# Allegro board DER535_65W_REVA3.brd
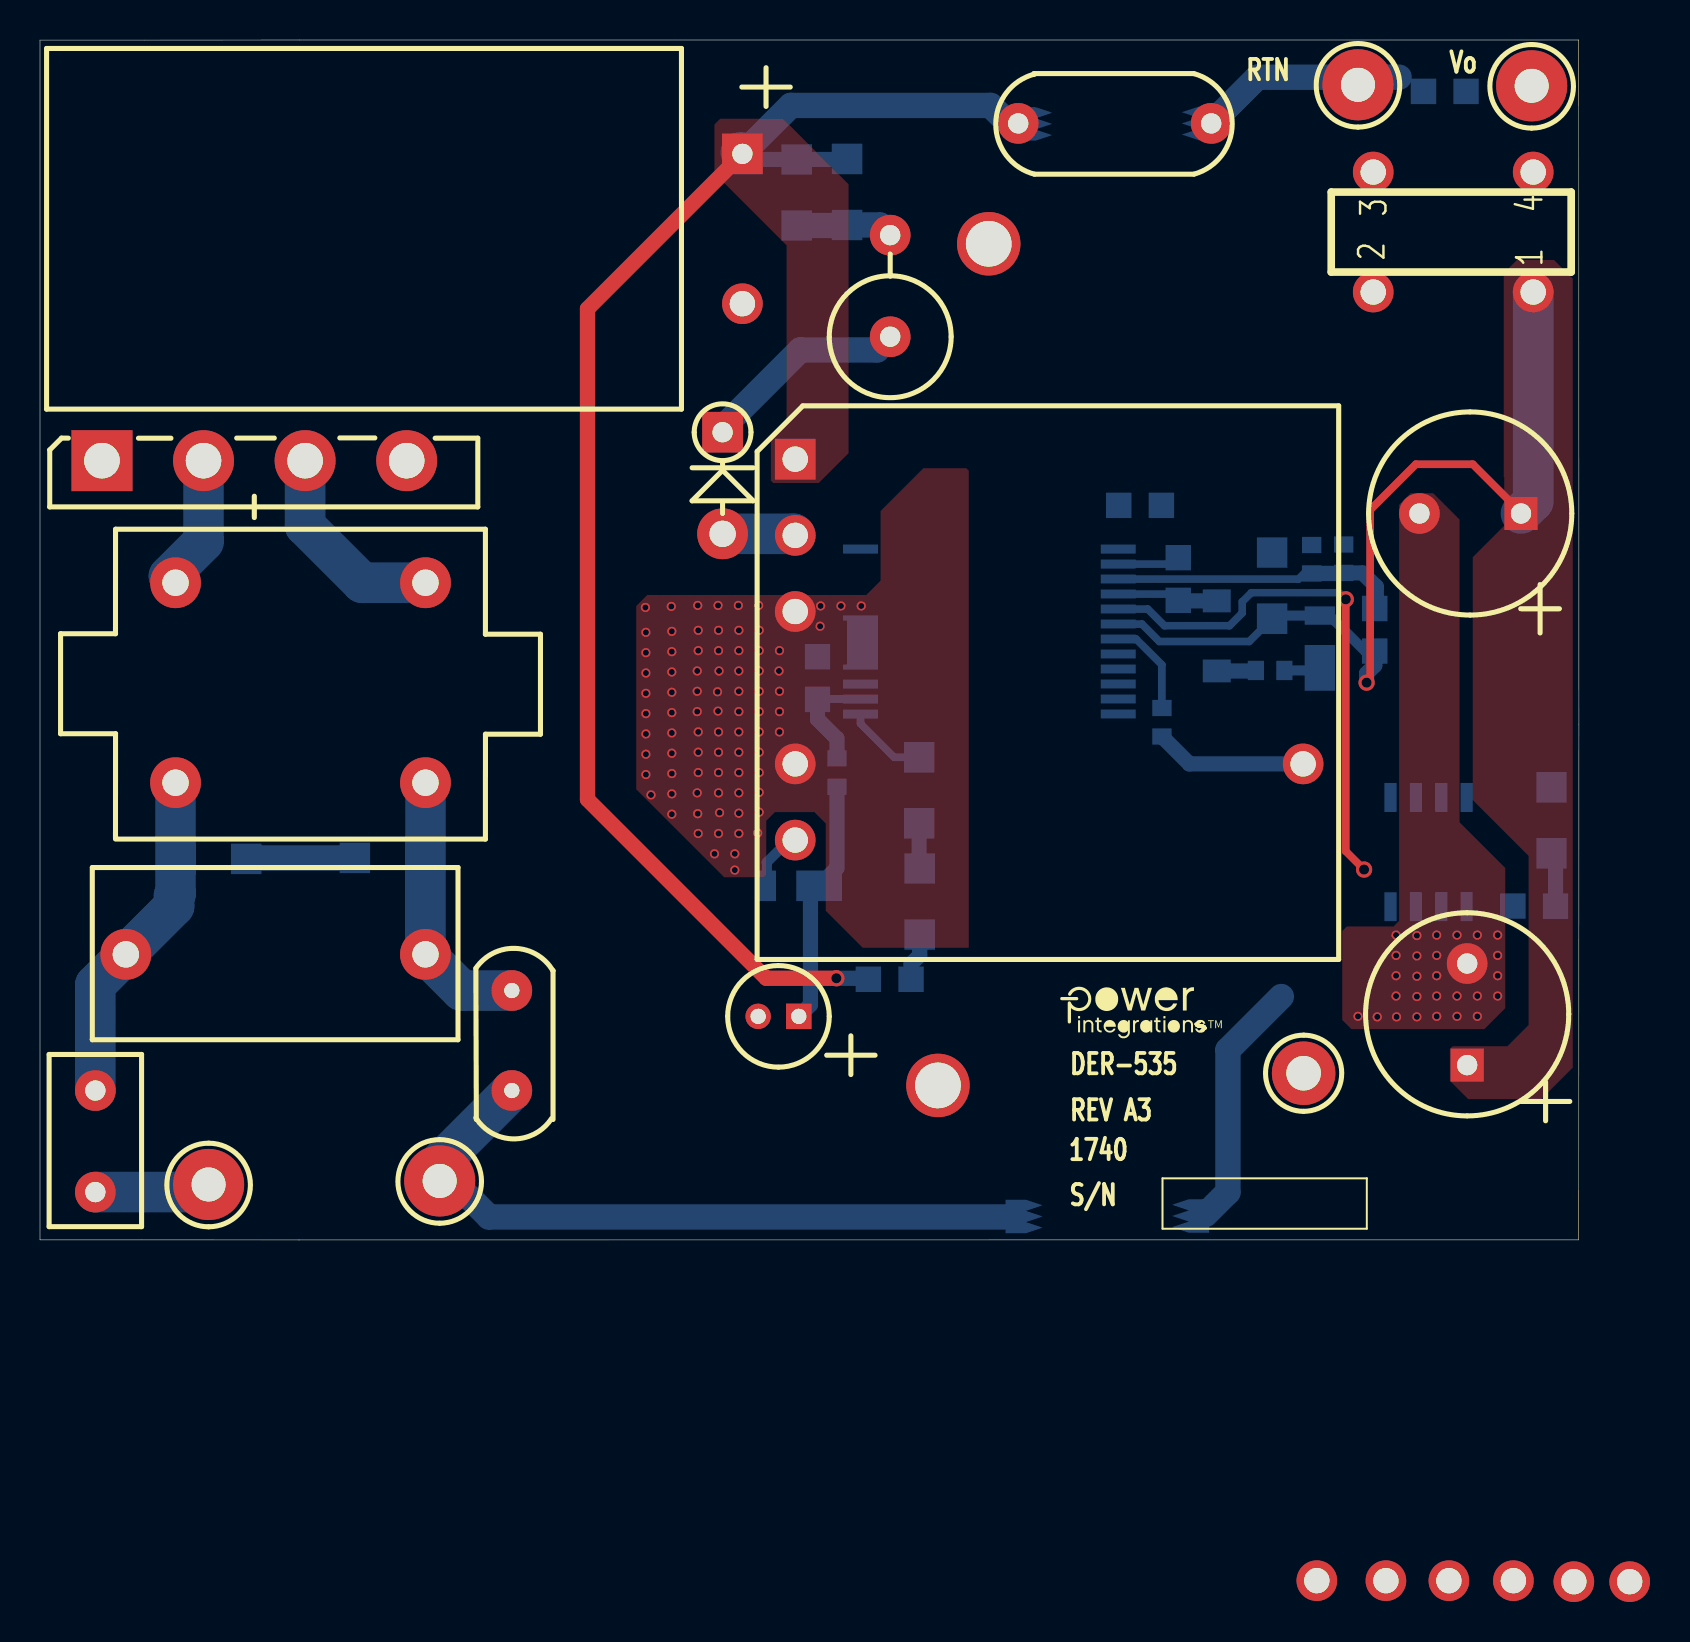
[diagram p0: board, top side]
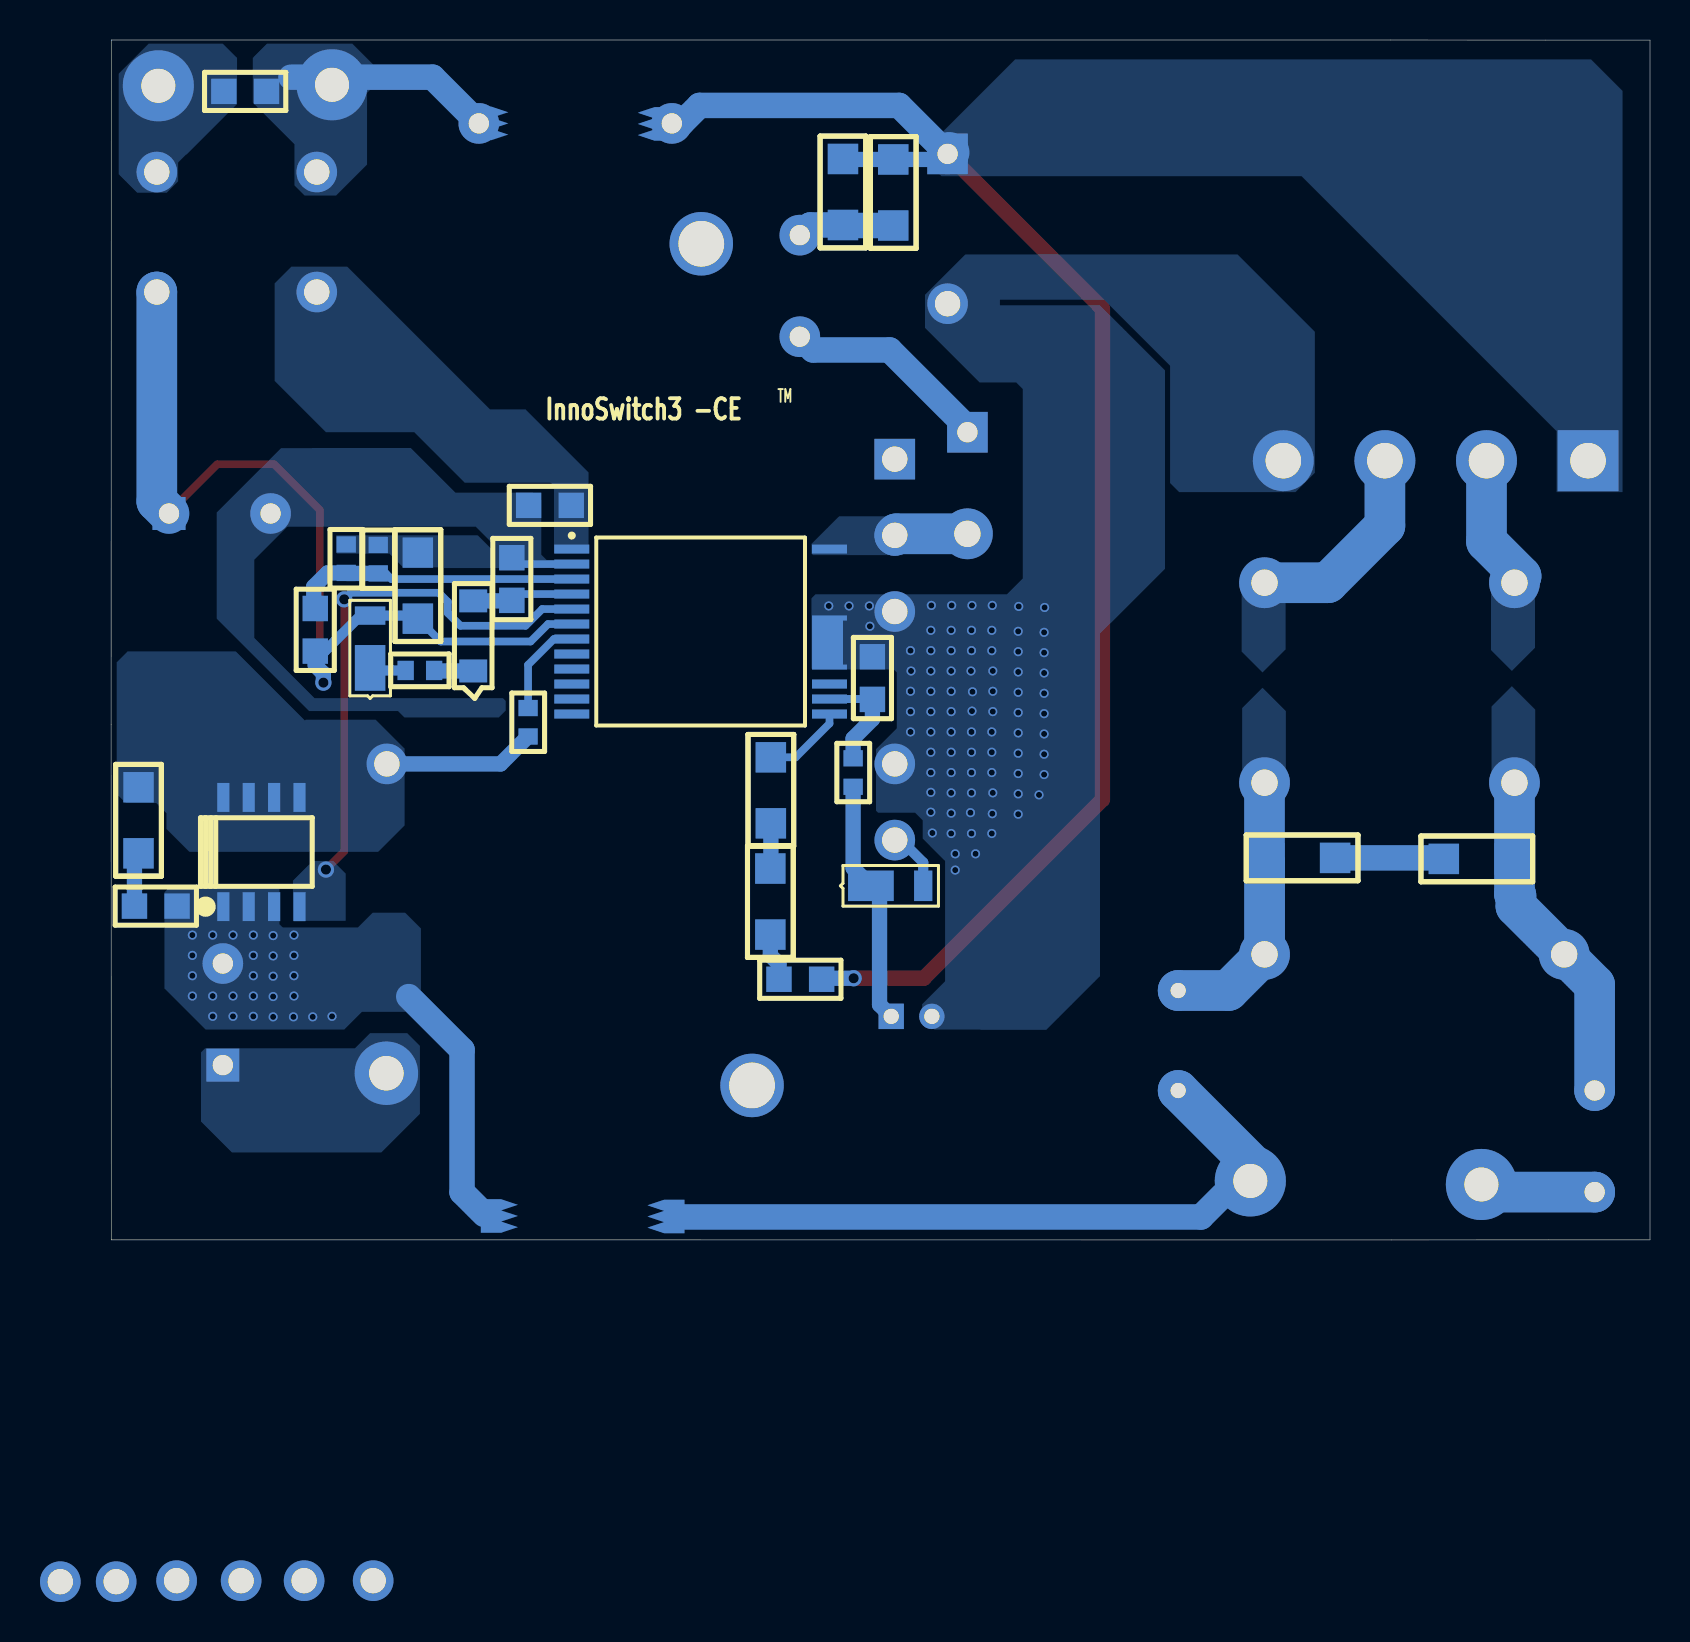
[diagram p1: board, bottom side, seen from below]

Outline 76.96 x 60 mm; copper layers: TOP, BOTTOM. Coordinates in mm from the lower left corner of the outline.
Outline path: 0,60 5.23,60 12.95,60 76.95,60 76.96,25.79 76.95,0 12.95,0 5.08,0 0,0 0,60

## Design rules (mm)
constraint set DEFAULT: min track width 0.508

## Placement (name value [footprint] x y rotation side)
BR1  GBU4J-BP  [PIDAXBRIDGEGBU8]  3.1 38.97 0 top
C1  220 nF  [PINPXCAPRAD720X340590040]  4.29 14.28 0 top
C2  120 uF  [PIPOLCAPD710LS3000401400LHORIZ]  35.13 54.31 270 top
C3  2.2 nF  [PISMC1206]  37.85 50.73 90 bottom
C4  22 uF  [PIPOLCAPCLYD200LS80030]  37.95 11.18 180 top
C5  4.7 uF  [PISMC0805]  38.89 27.03 90 bottom
C6  680 pF  [PINPYCAPRAD470X210LS380040]  48.92 55.83 0 top
C7  2.2 uF  [PISMC0805]  56.92 34.12 270 bottom
C8  10 nF  [PISMC1206]  61.62 34.37 270 bottom
C9  330 pF  [PISMC0603]  63.6 34.75 270 bottom
C10  2.2 nF  [PISMC0805]  75.79 16.69 180 bottom
C11  560 uF  [PIPOLCAPCYLD400LS200040]  71.37 8.74 90 top
C12  560 uF  [PIPOLCAPCYLD400LS200040]  74.07 36.33 180 top
C14  1 uF  [PISMC0805]  71.32 57.43 180 bottom
D1  FR107G  [PIDV200X110X040DO41]  34.14 40.39 270 top
D2  DFLR1200-7  [PISMDDFLR120012]  38.99 17.71 0 bottom
D3  DFLR1200-7  [PISMDDFLR120012]  64.01 28.58 270 bottom
F1  3.15 A  [PI_RST_MICROFUSE]  2.77 7.47 270 top
FL1  Hole_70mils  [PI_HOLE_70MIL]  63.2 8.31 0 top
L  BLK  [PITPKEYSTONE125X125]  8.43 2.77 0 top
L1  15 mH  [PIIND4P944X650LS492X394031]  19.28 22.86 180 top
L2  155 uH  [PI_TOROID_CMC_DER535]  74.68 47.4 90 top
MTG_HOLE1  No 2  [PIMTGHOLE2]  47.45 49.81 0 top
MTG_HOLE2  No 2  [PIMTGHOLE2]  44.91 7.73 0 top
N  WHT  [PITPKEYSTONE125X125]  19.99 2.95 0 top
NOREF  -  []  -137.83 54.24 0 top
NOREF#2  -  []  50.47 12.55 0 top
NOREF#3  -  []  0 60 0 top
NOREF#4  -  []  0 0 90 top
NOREF#5  -  []  -215.65 -144.78 0 top
Q1  AO4294  [PISMSO8]  71.35 16.67 180 bottom
R1  1.5 M  [PISMR1206]  7.01 19.05 0 bottom
R2  2 M  [PISMR1206]  15.75 19.11 0 bottom
R3  100 k  [PISMR1206]  40.36 54.06 270 bottom
R4  47  [PI_2W_VRES240LS200D040]  42.52 45.17 90 top
R5  5.1 k  [PISMR0603]  39.85 22.66 90 bottom
R6  49.9 k  [PISMR0805]  41.43 13.03 0 bottom
R7  1.80 M  [PISMR1206]  43.99 15.27 90 bottom
R8  1.80 M  [PISMR1206]  43.97 20.83 90 bottom
R9  47  [PISMR0603]  56.11 25.18 90 bottom
R10  0.007  [PISMR0805]  56.08 36.73 180 bottom
R11  12  [PISMR1206]  75.59 19.33 90 bottom
R12  100  [PISMR0603]  60.81 28.48 0 bottom
R13  143 k  [PISMR0805]  66.75 29.44 90 bottom
R14  10 k  [PISMR0603]  65.2 33.35 90 bottom
RT1  2.5  [PI_RAD150X300LS200D030]  23.6 7.47 90 top
T1  PQ26/20  [PI_BOBBIN_BPQ26_20_12P]  37.77 39.04 0 top
TP3  RED  [PITPKEYSTONE125X125]  74.6 57.71 0 top
TP4  BLK  [PITPKEYSTONE125X125]  65.91 57.76 0 top
U1  INN3168C  [PI_IC_INSOP_24B]  53.92 34.55 180 bottom
VR1  MMSZ5248B-7-F  [PI_SM_SOD-123_12]  58.85 28.45 90 bottom

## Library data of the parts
BR1 = DISCRETE BRIDGE_+~~-
C1 C3 C5-C10 C14 = CAP NP
C2 = CAP POL: alternate symbols: (pipolcapd710ls3000401400lhoriz)
C4 = CAP POL: alternate symbols: (pipolcapclyd200ls80030h)
C11 C12 = CAP POL: alternate symbols: (pipolcapcyld400ls2000401000h)
D1 = DIODE: alternate symbols: (pidax475x125040do41,pidv200x110x040do41wbead,pidax390x125040do41)
D2 D3 = DIODE
F1 = FUSE: alternate symbols: (pirstmicrofusehoz)
FL1 = FlyingLead
L N TP3 TP4 = TESTPOINT
L1 = INDUCTOR_4P_revD
L2 = TORRID 4P_14_23
MTG_HOLE1 MTG_HOLE2 = MTG_HOLE_2-56
Q1 = FET_N_SGD_123_4_5678
R1-R3 R5-R14 = R
R4 = R: alternate symbols: (PI_2W_RES240LS500D040,pi_2w_resd145ls455d040)
RT1 = THERMISTOR: alternate symbols: (pirad400x300ls200040_h)
T1 = BPQ26/20_12P/GENERIC
U1 = DEV_InSOP_0
VR1 = DIODE_ZENER

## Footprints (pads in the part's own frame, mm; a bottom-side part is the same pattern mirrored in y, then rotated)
PI_2W_VRES240LS200D040
  round 2.032 hole 1.016: 1(0,0) 2(5.08,0)
PI_BOBBIN_BPQ26_20_12P
  rect 2.032x2.032 hole 1.27: 1(0,0)
  round 2.032 hole 1.27: 2(0,-3.81) 3(0,-7.62) 4(0,-15.24) 5(0,-19.05) 6(26.086,-56.083) 7(32.69,-56.083) 8(29.54,-56.083) 9(25.4,-15.24) 10(41.732,-56.134) 11(38.938,-56.134) 12(35.916,-56.083)
PI_HOLE_70MIL
  round 3.175 hole 1.727: 1(0,0.025)
PI_IC_INSOP_24B
  rect 1.75x0.45 smd: 1(0,0) 2(0,-0.75) 3(0,-1.5) 4(0,-2.25) 5(0,-3) 6(0,-3.75) 7(0,-4.5) 8(0,-5.25) 9(0,-6) 10(0,-6.75) 11(0,-7.5) 12(0,-8.25) 13(12.89,-8.25) 14(12.89,-7.5) 15(12.89,-6.75) 24(12.89,0)
  custom 0.437x0.437 smd: 16(12.89,-4.67)
PI_RAD150X300LS200D030
  round 2.032 hole 0.762: 1(0,0) 2(5,0)
PI_RST_MICROFUSE
  round 2.032 hole 1.016: 1(0,0) 2(5.08,0)
PI_SM_SOD-123_12
  rect 1.143x1.397 smd: 1(0,0) 2(3.505,0)
PI_TOROID_CMC_DER535
  round 2.032 hole 1.27: 1(0,0) 2(0,8) 3(6,8) 4(6,0)
PIDAXBRIDGEGBU8
  rect 3.048x3.048 hole 1.778: 1(0,0)
  round 3.048 hole 1.778: 2(5.08,0) 3(10.16,0) 4(15.24,0)
PIDV200X110X040DO41
  rect 2.032x2.032 hole 1.016: 1(0,0)
  round 2.54 hole 1.321: 2(5.08,0)
PIIND4P944X650LS492X394031
  round 2.54 hole 1.321: 1(12.5,-10) 2(12.5,0) 3(0,0) 4(0,-10)
PIMTGHOLE2
  round 3.175 hole 2.286: 1(0,0)
PINPXCAPRAD720X340590040
  round 2.54 hole 1.321: 1(0,0) 2(14.986,0)
PINPYCAPRAD470X210LS380040
  round 2.032 hole 1.016: 1(0,0) 2(9.652,0)
PIPOLCAPCLYD200LS80030
  rect 1.27x1.27 hole 0.762: 1(0,0)
  round 1.27 hole 0.762: 2(2.032,0)
PIPOLCAPCYLD400LS200040
  rect 1.651x1.651 hole 1.016: 1(0,0)
  round 2.032 hole 1.016: 2(5.08,0)
PIPOLCAPD710LS3000401400LHORIZ
  rect 2.032x2.032 hole 1.016: 1(0,0)
  round 2.032 hole 1.27: 2(7.493,0)
PISMC0603
  rect 0.813x0.965 smd: 1(0,0) 2(1.422,0)
PISMC0805
  rect 1.27x1.27 smd: 1(0,0) 2(2.134,0)
PISMC1206
  rect 1.524x1.524 smd: 1(0,0) 2(3.302,0)
PISMDDFLR120012
  rect 2.286x1.524 smd: 1(-0.025,0)
  rect 0.914x1.524 smd: 2(-2.642,0)
PISMR0603
  rect 0.813x0.965 smd: 1(0,0) 2(1.422,0)
PISMR0805
  rect 1.27x1.27 smd: 1(0,0) 2(2.134,0)
PISMR1206
  rect 1.524x1.524 smd: 1(0,0) 2(3.302,0)
PISMSO8
  rect 0.61x1.448 smd: 1(0,0) 2(1.27,0) 3(2.54,0) 4(3.81,0) 5(3.81,5.461) 6(2.54,5.461) 7(1.27,5.461) 8(0,5.461)
PITPKEYSTONE125X125
  round 3.556 hole 1.702: 1(0,0)

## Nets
NC8: U1.8
NC9: U1.9
NC10: U1.10
NC11: U1.11
NC12: U1.12
NC15: U1.15
N2987702: BR1.1 C2.1 C3.2 C6.1 R3.1 R6.1 T1.1
N2987790: BR1.2 L1.1
N2987798: N.1 RT1.1
N2987826: F1.2 L.1
N10910152: R9.2 U1.7
N10910164: C3.1 R3.2 R4.2
N10910168: L2.2 R10.2 U1.1
N10910222: C7.1 C8.1 C9.1 C10.2 C11.2 C12.2 Q1.1 Q1.2 Q1.3(S3) R10.1 R14.2 U1.2
N10910248: Q1.4 U1.5
N10910298: C5.1 R5.2 U1.14
N10910306: C8.2 C11.1 C12.1 D3.2 FL1.1 L2.1 R13.1 U1.6
N10910326: BR1.4 C2.2 C4.2 C5.2 T1.3 T1.4 U1.16
N10910384: C9.2 R13.2 R14.1 U1.3
N10910392: R8.2 U1.13(VPIN)
N10910464: D2.2 T1.5
N10910558: C10.1 R11.1
N10910618: R7.2 R8.1
N10910664: C6.2 C14.2 L2.3 TP4.1
N10911024: C7.2 U1.4 VR1.2
N10911106: C4.1 D2.1 R5.1
N10913618: D1.1 R4.1
N10913908: D1.2 T1.2 U1.24
N10921396: C1.2 L1.3 R2.2 RT1.2
N10932979: C14.1 L2.4 TP3.1
N10933272: Q1.5 Q1.6 Q1.7 Q1.8 R9.1 R11.2 T1.9
N10975944: C1.1 F1.1 L1.2 R1.1
N10976231: BR1.3(AC2) L1.4
N10995479: R1.2 R2.1
N11000162: R12.1 VR1.1
N11000879: R6.2 R7.1
N11102383: D3.1 R12.2

Pads without a net: MTG_HOLE1 1; MTG_HOLE2 1; T1 6 7 8 10 11 12

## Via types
v1: diameter 0.457, hole 0.305, TOP to BOTTOM, 108 vias
v2: diameter 0.813, hole 0.508, TOP to BOTTOM, 4 vias

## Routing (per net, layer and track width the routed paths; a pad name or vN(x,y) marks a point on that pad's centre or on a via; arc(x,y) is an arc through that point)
N2987702: length 73.9
  TOP w0.762: C2.1 27.38,46.56 27.38,22.03 36.32,13.09 v2(39.83,13.09)
  BOTTOM w0.762: R3.1 40.34,54.03 C3.2 35.41,54.03 C2.1 ; v2(39.83,13.09) 41.38,13.09 R6.1
  BOTTOM w1.27: C2.1 37.55,56.73 47.54,56.73 48.44,55.83 C6.1
  BOTTOM w2.032: 35.05,54.39 C2.1
N2987790: length 7
  BOTTOM w2.032: L1.1 6.45,33.19 8.18,34.92 BR1.2
N2987798: length 36.3
  BOTTOM w1.27: 19.79,3.66 19.99,3.46 N.1 ; 48.54,1.15 22.45,1.15 20.45,3.15 19.79,3.15
  BOTTOM w2.032: RT1.1 19.79,3.66 19.79,3.15
N2987826: length 6.4
  BOTTOM w1.27: 7.62,2.39 8.05,2.39 L.1
  BOTTOM w2.032: F1.2 7.62,2.39 7.9,2.67 8.13,2.67
N10910152: length 4.9
  BOTTOM w0.381: U1.7 54.82,30.05 56.11,28.76 R9.2
N10910164: length 5.1
  BOTTOM w1.27: 40.34,50.73 R3.2 42.01,50.75 R4.2 ; 40.34,50.73 40.51,50.73 ; 40.34,50.73 C3.1
N10910222: length 15.7
  BOTTOM w0.381: U1.2 56.86,33.8 56.92,33.86 C7.1
  BOTTOM w1.27: 58.29,1.27 59.41,2.39 59.41,9.5 62.08,12.17
  vias: v1(65.91,11.18) v1(66.88,11.15) v1(67.82,15.24) v1(67.82,14.23) v1(67.82,13.21) v1(67.82,12.2) v1(67.84,11.15) v1(68.86,15.22) v1(68.86,14.2) v1(68.86,13.19) v1(68.86,12.17) v1(68.86,11.15) v1(69.85,15.24) v1(69.85,14.23) v1(69.85,13.21) v1(69.85,12.2) v1(69.85,11.18) v1(70.87,15.24) v1(70.87,12.2) v1(70.87,11.18) v1(71.88,15.24) v1(71.88,12.2) v1(71.88,11.18) v1(72.9,15.24) v1(72.9,14.23) v1(72.9,13.21) v1(72.9,12.2)
N10910248: length 26.8
  TOP w0.381: v2(66.22,18.52) 65.3,19.44 v2(65.3,32.03)
  BOTTOM w0.381: v2(65.3,32.03) 64.97,32.36 60.58,32.36 60.12,31.91 60.12,31.35 59.49,30.71 56.24,30.71 55.4,31.55 U1.5
N10910298: length 7.7
  BOTTOM w0.381: 38.91,27.05 41.06,27.05 U1.14 38.91,27.05 ; 38.91,27.05 C5.1
  BOTTOM w0.762: R5.2 39.85,25.07 38.89,26.04 C5.1
N10910306: length 45.8
  TOP w0.381: v2(66.34,27.87) 66.52,28.05 66.52,36.5 68.81,38.79 71.65,38.79 74.09,36.35 C12.1
  BOTTOM w0.381: C8.2 60.48,29.93 55.98,29.93 55.11,30.8 U1.6
  BOTTOM w0.508: R13.1 66.27,29.44 64.49,31.22 D3.2 61.77,31.22 C8.2
  BOTTOM w0.762: v2(66.34,27.87) 66.34,28.33 66.75,28.73 R13.1
  BOTTOM w2.032: C12.1 74.68,36.94 L2.1
N10910326:
  vias: v1(30.28,31.63) v1(30.3,30.38) v1(30.3,29.37) v1(30.3,28.35) v1(30.3,27.33) v1(30.3,26.32) v1(30.3,25.3) v1(30.3,24.29) v1(30.3,23.27) v1(30.56,22.25) v1(31.57,31.68) v1(31.6,30.43) v1(31.6,29.42) v1(31.6,28.4) v1(31.6,27.39) v1(31.6,26.37) v1(31.6,25.35) v1(31.6,24.34) v1(31.6,23.32) v1(31.6,22.31) v1(31.6,21.29) v1(32.89,31.73) v1(32.92,30.48) v1(32.92,29.47) v1(32.87,28.45) v1(32.87,27.44) v1(32.87,26.42) v1(32.92,25.4) v1(32.92,24.39) v1(32.92,23.37) v1(32.87,22.36) v1(32.89,21.31) v1(32.92,20.32) v1(33.73,19.31) v1(33.91,31.73) v1(33.93,30.48) v1(33.93,29.47) v1(33.88,27.41) v1(33.91,26.45) v1(33.93,25.4) v1(33.93,24.39) v1(33.93,23.37) v1(33.93,22.36) v1(33.93,20.32) v1(33.96,28.45) v1(33.99,21.37) v1(34.75,19.31) v1(34.75,18.5) v1(34.92,31.73) v1(34.95,30.48) v1(34.95,29.47) v1(34.95,28.45) v1(34.95,27.44) v1(34.95,26.42) v1(34.95,25.4) v1(34.95,24.39) v1(34.95,23.37) v1(34.95,22.36) v1(34.95,21.34) v1(34.95,20.32) v1(35.94,31.73) v1(35.89,20.35) v1(35.97,30.48) v1(35.97,29.47) v1(35.97,28.45) v1(35.97,27.44) v1(35.97,26.42) v1(35.97,25.4) v1(35.97,24.39) v1(35.97,23.37) v1(35.97,22.38) v1(35.97,21.39) v1(36.98,29.47) v1(36.96,28.45) v1(36.98,27.44) v1(36.98,26.42) v1(36.98,25.4) v1(39.04,31.7) v1(39.01,30.69) v1(40.06,31.7) v1(41.07,31.7)
N10910384: length 14.4
  BOTTOM w0.381: C9.2 63.22,33.33 62.94,33.05 U1.3
  BOTTOM w0.762: R13.2 66.83,31.65 66.83,32.67 66.14,33.35 R14.1 65.18,33.33 C9.2
N10910392: length 4.1
  BOTTOM w0.381: U1.13 41.03,25.82 42.72,24.13 R8.2
N10910464: length 3.1
  BOTTOM w0.508: T1.5 37.47,19.99 36.35,18.88 D2.2
N10910558: length 2.7
  BOTTOM w0.762: C10.1 75.79,19.13 R11.1
N10910618: length 2.3
  BOTTOM w0.762: R7.2 43.97,18.6 R8.1
N10910664: length 10.9
  BOTTOM w1.27: 67.97,58.14 66.29,58.14 ; 66.29,58.14 60.88,58.14 C6.2 ; 66.29,58.14 TP4.1
N10911024: length 5.2
  BOTTOM w0.381: C7.2 56.97,32.03 56.97,32.14 56.81,32.3 U1.4
  BOTTOM w0.762: VR1.2 56.95,31.96 C7.2
N10911106: length 12.3
  BOTTOM w0.762: C4.1 38.53,11.76 38.53,17.28 D2.1 39.85,18.6 R5.1
N10913618: length 10.5
  BOTTOM w1.27: R4.1 41.86,44.51 38.02,44.51 34.14,40.62 D1.1
N10913908: length 3.7
  BOTTOM w2.032: D1.2 37.69,35.31 T1.2
N10921396: length 18.8
  BOTTOM w1.27: 19.16,14.28 18.9,14.54 18.9,18.95 R2.2
  BOTTOM w2.032: RT1.2 21.09,12.47 C1.2 19.16,14.28 19.28,14.4 L1.3
N10933272: length 7.6
  BOTTOM w0.762: T1.9 57.48,23.8 R9.1
N10975944: length 19
  BOTTOM w1.27: R1.1 6.71,18.75 6.71,17.23
  BOTTOM w2.032: L1.2 6.78,17.3 6.71,17.23 6.71,16.69 C1.1 2.77,12.76 F1.1
N10976231: length 10.5
  BOTTOM w2.032: BR1.3 13.26,35.72 16.11,32.86 L1.4
N10995479: length 5.5
  BOTTOM w1.27: R1.2 10.36,19.11 R2.1
N11000162: length 2
  BOTTOM w0.762: VR1.1 60.78,28.45 R12.1
N11000879: length 2.4
  BOTTOM w0.762: R7.1 43.99,14.23 43.56,13.8 R6.2
N11102383: length 1.8
  BOTTOM w0.508: D3.1 63.88,28.48 R12.2

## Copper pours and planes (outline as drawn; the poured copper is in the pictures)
Net_45 on BOTTOM (solid shape): 50.14,1.73 49.3,1.45 50.14,1.17 49.3,0.89 50.14,0.61 49.3,0.33 48.29,0.33 48.29,2.01 49.3,2.01
Net_45 on BOTTOM (solid shape): 50.62,56.37 49.78,56.09 50.62,55.81 49.78,55.53 50.62,55.25 49.78,54.97 48.77,54.97 48.77,56.65 49.78,56.65
Net_45 on BOTTOM (solid shape): 58.47,0.36 57.45,0.36 56.62,0.64 57.45,0.92 56.62,1.2 57.45,1.48 56.62,1.76 57.45,2.04 58.47,2.04
Net_45 on BOTTOM (solid shape): 58.95,55 57.94,55 57.1,55.27 57.94,55.55 57.1,55.83 57.94,56.11 57.1,56.39 57.94,56.67 58.95,56.67
N2987702 on TOP: 34.01,56.06 37.16,56.06 40.44,52.79 40.44,39.35 38.94,37.85 36.68,37.85 36.55,37.98 36.55,40.01 37.34,40.8 37.34,49.74 33.73,53.34 33.73,55.78
N2987702 on BOTTOM: 1.37,37.39 1.37,57.46 2.95,59.03 31.75,59.03 35.53,55.25 35.53,53.29 35.43,53.19 17.42,53.19 4.67,40.44 4.67,37.39
N2987790 on BOTTOM: 5.75,29.61 6.91,28.45 7.95,29.49 7.95,33.23 7.94,33.24 7.94,33.79 6.05,33.79 5.75,33.49
N10910168 on BOTTOM: 53.09,34.35 53.09,38.38 56.24,41.53 58.01,41.53 65.15,48.67 67.94,48.67 68.78,47.83 68.78,42.96 66.22,40.39 61.8,40.39 59.27,37.86 54.98,37.86 54.81,37.7 54.81,34.35
N10910222 on TOP: 65.35,15.68 65.13,15.45 65.13,11 65.58,10.55 72.24,10.55 73.28,11.59 73.28,18.6 70.99,20.88 70.99,36.02 69.67,37.34 68.55,37.34 67.97,36.76 67.97,15.96 67.69,15.68
N10910222 on BOTTOM: 57.78,34.24 57.94,34.24 57.94,34.55 58.62,35.23 65.71,35.23 65.71,34.37 65.66,34.32 63.04,34.32 62.36,33.63 60.6,33.63 60.58,33.61 60.58,33.6 55.26,33.6 55.12,33.74 55.12,33.94 55.45,34.27 55.45,36.99 55.83,37.37 59.74,37.37 61.98,39.6 66.9,39.6 66.92,39.59 68.47,39.59 71.68,36.38 71.68,31.07 67.06,26.45 62.61,26.45 62.29,26.13 57.57,26.13 57.23,26.47 57.23,26.95 57.37,27.09 66.79,27.09 69.8,30.1 69.8,34.01 68.15,35.67 58.72,35.67 57.78,34.73
N10910222 on BOTTOM: 72.24,10.52 65.3,10.52 64.41,11.41 62.15,11.41 61.47,12.09 61.47,15.57 62.26,16.36 63.88,16.36 64.62,15.63 68.38,15.63 68.54,15.79 68.54,17.67 68.61,17.73 73.94,17.73 74.3,17.38 74.3,12.58
N10910248 on BOTTOM: 67.84,15.96 67.87,15.98 67.87,17.96 66.88,18.95 65.86,18.95 65.23,18.32 65.23,15.98 65.25,15.96
N10910306 on TOP: 76.66,8.61 75.08,7.04 71.42,7.04 70.51,7.95 70.51,9.55 70.64,9.68 73.38,9.68 74.45,10.75 74.45,19.21 71.65,22 71.65,34.14 73.23,35.72 73.23,38.13 73.2,38.16 73.2,48.34 73.86,49 75.72,49 76.66,48.06
N10910306 on BOTTOM: 70.92,4.37 63.45,4.37 61.52,6.3 61.52,9.71 62.15,10.34 64.01,10.34 64.77,9.58 72.26,9.58 72.47,9.38 72.47,5.92
N10910326 on TOP: 36.75,21.39 38.73,21.39 39.29,20.83 39.29,16.46 41.15,14.61 46.45,14.61 46.45,38.47 46.33,38.59 44.17,38.59 42.04,36.45 42.04,32.96 41.33,32.25 30.37,32.25 29.82,31.7 29.82,22.53 34.21,18.14 36.2,18.14 36.32,18.27 36.32,20.96
N10910326 on BOTTOM: 30.19,10.51 27.51,13.19 27.51,30.31 24.26,33.56 24.26,43.49 27.51,46.74 32.51,46.74 32.51,47.02 27.3,47.02 24,43.72 24,37.85 23.55,37.39 17.73,37.39 16.76,38.36 16.76,45.42 20.62,49.28 34.24,49.28 36.26,47.26 36.26,45.61 33.53,42.88 31.7,42.88 31.37,42.55 31.37,33.07 32.16,32.29 41.73,32.29 41.94,32.08 41.94,28.58 41.88,28.53 37.82,28.53 37.67,28.38 37.67,25.58 38.71,24.54 38.71,21.47 38.61,21.37 36.75,21.37 36.37,20.98 36.37,20.07 35.26,18.95 35.26,12.93 36.4,11.79 36.4,11.13 35.79,10.52 33.5,10.52 33.49,10.51
N10910664 on BOTTOM: 65.71,52.23 64.16,53.78 64.16,57.36 63.4,58.12 63.4,58.32 64.9,59.82 69.16,59.82 69.88,59.11 69.88,56.87 67.79,54.79 67.79,52.73 67.28,52.23
N10913908 on BOTTOM: 41.94,34.8 41.94,34.32 41.86,34.24 37.39,34.24 36.83,34.8 36.83,35.62 37.4,36.19 40.55,36.19
N10921396 on BOTTOM: 20.4,26.6 19.38,27.61 18.21,26.45 18.21,22.66 18.24,22.69 20.4,22.69
N10932979 on BOTTOM: 76.58,53.29 75.65,52.37 74.18,52.37 73.61,52.94 73.61,53.88 73.2,54.28 73.18,54.28 70.66,56.8 70.66,59.11 71.37,59.82 75.08,59.82 76.58,58.32
N10933272 on BOTTOM: 62.28,24.57 63.73,26.01 67.23,26.01 67.27,25.98 70.73,29.43 76.14,29.43 76.68,28.88 76.68,22.31 76.23,21.85 74.7,21.85 74.19,21.34 74.19,20.55 73.05,19.41 63.6,19.41 62.28,20.73
N10975944 on BOTTOM: 7.92,26.67 6.91,27.69 5.74,26.52 5.74,22.66 7.92,22.66
N10976231 on BOTTOM: 18.22,29.53 19.38,28.38 20.42,29.42 20.42,33.15 20.38,33.19 20.38,33.46 18.26,33.46 18.22,33.42

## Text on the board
Ref Des/Silkscreen Bottom: TM | InnoSwitch3 -CE
Ref Des/Silkscreen Top: 1740 | S/N | DER-535 | REV A3 | RTN | Vo
User.6: 14. FAB HOUSE LOGO,DATE CODE TO BE IN SILK SCREEN ONLY.DO NOT USE COPPER. | PLEASE DELETE THESE PINS | 13   MATERIAL FR4 COPPER 2oz THICKNESS 0.062"
User.8: FIGURE | FINISHED_SIZE | 12.0 | 20.0 | 30.0 | 40.0 | 50.0 | 52.0 | 67.0 | 68.0 | 70.0 | 90.0 | DRILL CHART: TOP to BOTTOM | ALL UNITS ARE IN MILS | PLATED | QTY | 108 | 4 | 12 | 17 | 7 | 1 | 2
